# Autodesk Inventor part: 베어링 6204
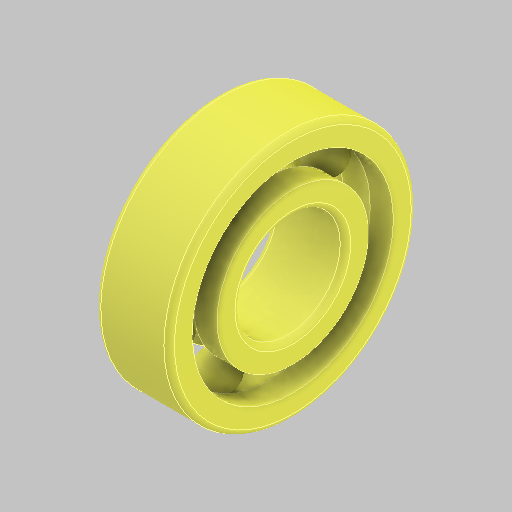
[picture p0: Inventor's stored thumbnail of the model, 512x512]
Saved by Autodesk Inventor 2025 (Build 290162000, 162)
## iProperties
Created: 2024-08
Part Number: 베어링 6204
Material: 스테인리스강
Description: 깊은 그루브 볼 베어링
Document SubType Name: Modeling
Designer: 현기
Density: 8.08 g/cm^3
Appearance: 기본값
Author: jhkim
Sending System: Autodesk Inventor 2025
Preprocessor: ST-DEVELOPER v20
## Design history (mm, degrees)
feature "Solid1"
feature "Solid1:1"
feature "Solid1:2"
feature "Solid1:3"
feature "Solid1:4"
feature "Solid1:5"
feature "Solid1:6"
feature "Solid1:7"
feature "Solid1:8"
node "솔리드1"
node "솔리드2"
node "솔리드3"
node "솔리드4"
node "솔리드5"
node "솔리드6"
node "솔리드7"
node "솔리드8"
node "솔리드9"
